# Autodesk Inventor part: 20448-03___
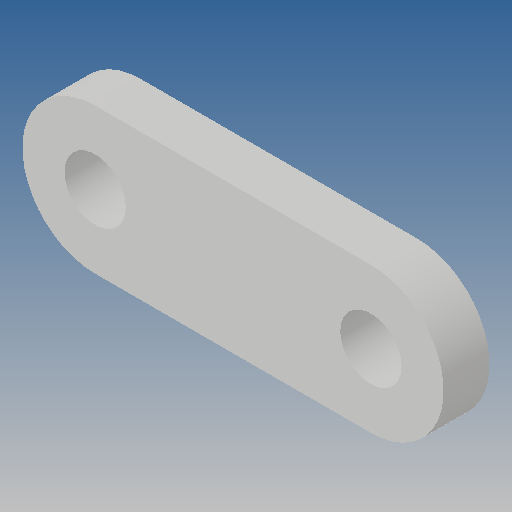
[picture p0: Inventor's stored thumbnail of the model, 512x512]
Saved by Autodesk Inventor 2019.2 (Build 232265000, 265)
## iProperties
Created: 2010-06
Part Number: 20448-03___
Material: Ogólny
Document SubType Name: Modeling
Designer: CADENGINEERING4
Density: 1 g/cm^3
Appearance: Domyślna
Author: CADENGINEERING4
Revision Number: ANY
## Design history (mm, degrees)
feature "NONE"
node "Bryła1"
